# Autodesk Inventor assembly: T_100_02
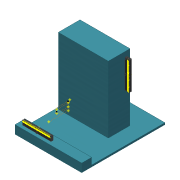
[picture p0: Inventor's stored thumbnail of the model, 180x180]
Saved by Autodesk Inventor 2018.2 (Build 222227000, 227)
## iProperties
Manager: www.cadconsulting.pl
Company: Fabian Stasiak CAD Consulting
Created: 2014-09
Part Number: T_100_02
Document SubType Name: Assembly
Designer: F.Stasiak
Catalog Web Link: www.expertbooks.pl
Author: F.Stasiak
Subject: Zbiór ćwiczeń. Autodesk Inventor 2020. Kurs Professional
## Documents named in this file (4)
- C:\ZCAI_2018_KPS\Wiązki\T_200_01.iam
- C:\ZCAI_2018_KPS\Wiązki\Komponenty\Konstrukcja_W2.ipt
- C:\ZCAI_2018_KPS\ContentCenter\pl-PL\Ribbon Cable Connector\Ribbon Cable Connector-13.ipt
- C:\ZCAI_2018_KPS\Wiązki\T_200_01\AIP\przewody i wiązki przewodów\T_200_01.Wiązka przewodów1.iam
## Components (4 placed, 3 different names)
1. Konstrukcja_W2:1 — Zestawiający:1, Równoległy:1, Zestawiający:2, Zestawiający:3, Zestawiający:4, Równoległy:2
2. Złącze kabla taśmowego Ribbon Cable Connector-13:1 — Zestawiający:1, Równoległy:1, Zestawiający:2
3. Złącze kabla taśmowego Ribbon Cable Connector-13:2 — Zestawiający:3, Zestawiający:4, Równoległy:2
4. Wiązka przewodów1 [sub-assembly]
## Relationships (6: Mate 4, Flush 2)
- Zestawiający:1 [Mate]: Konstrukcja_W2:1 ↔ Złącze kabla taśmowego Ribbon Cable Connector-13:1
- Równoległy:1 [Flush]: Konstrukcja_W2:1 ↔ Złącze kabla taśmowego Ribbon Cable Connector-13:1
- Zestawiający:2 [Mate]: Konstrukcja_W2:1 ↔ Złącze kabla taśmowego Ribbon Cable Connector-13:1
- Zestawiający:3 [Mate]: Konstrukcja_W2:1 ↔ Złącze kabla taśmowego Ribbon Cable Connector-13:2
- Zestawiający:4 [Mate]: Konstrukcja_W2:1 ↔ Złącze kabla taśmowego Ribbon Cable Connector-13:2
- Równoległy:2 [Flush]: Konstrukcja_W2:1 ↔ Złącze kabla taśmowego Ribbon Cable Connector-13:2
